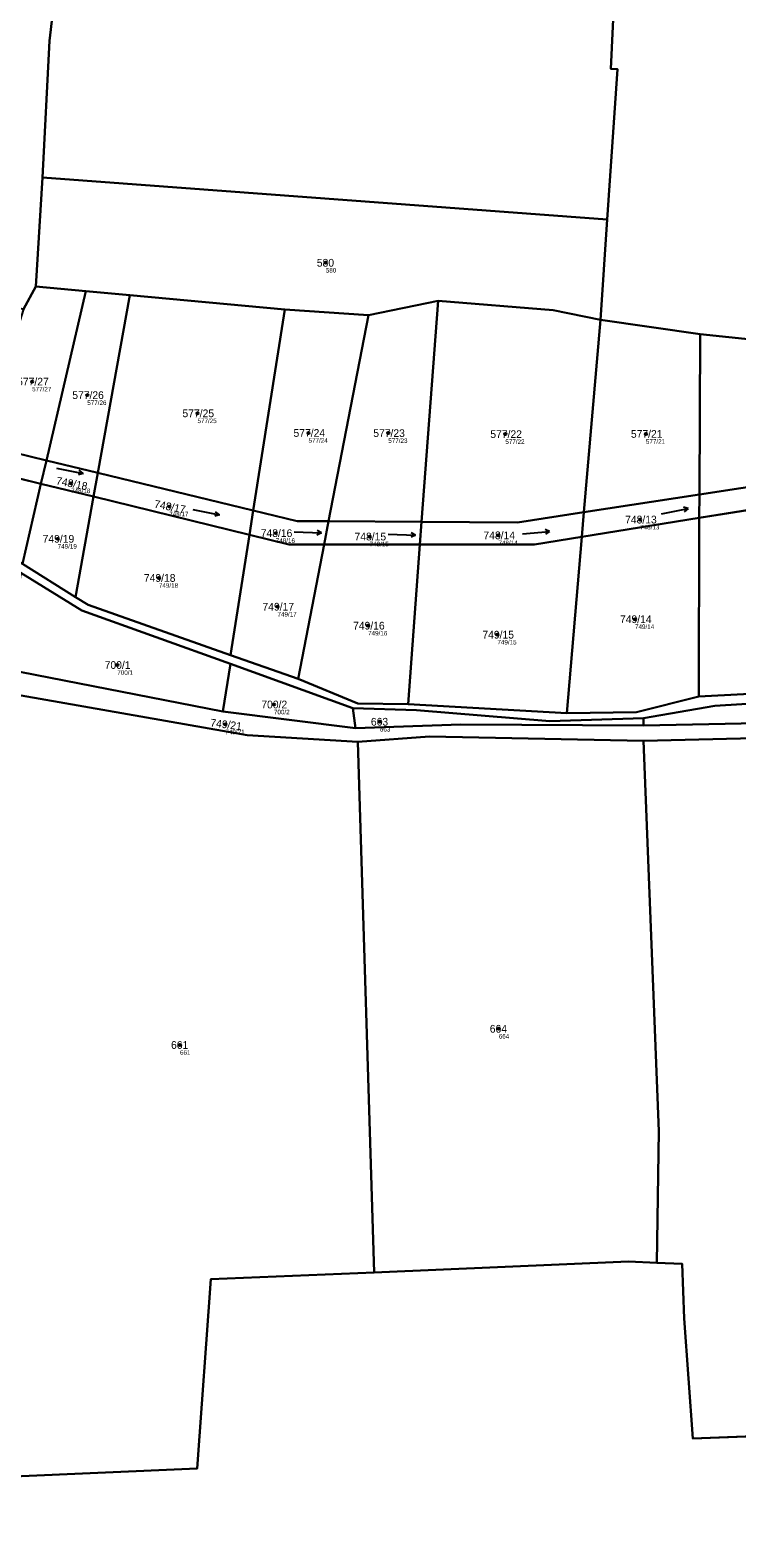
# Model space of a CAD drawing. Extents: x -767985 to -763816, y -1059600 to -1057360.
# Drawn here: x -764701.2 to -764545.8, y -1059400.7 to -1059068.8 of the extents above; entities that cross this region are included whole.
import ezdxf

# ---------------------------------------------------------------- set-up
doc = ezdxf.new("R2010")
doc.units = 0
for name, color, linetype in [('Definiční body', 7, 'Continuous'), ('Hranice parcel', 7, 'Continuous'), ('Parcelní čísla', 7, 'Continuous'), ('Polygon ku', 7, 'Continuous'), ('Polygon parcely', 7, 'Continuous'), ('Značky kultur', 7, 'Continuous')]:
    doc.layers.add(name, color=color, linetype=linetype)

msp = doc.modelspace()

# ---------------------------------------------------------------- linework, layer by layer
at = {"layer": 'Definiční body'}
for centre in [(-764636.2, -1059119.97994), (-764700.81, -1059146.14994), (-764688.68, -1059149.12994), (-764664.43, -1059153.12994), (-764640, -1059157.44994), (-764622.45, -1059157.48994), (-764596.69, -1059157.70994), (-764565.76, -1059157.65994), (-764692.24, -1059168.54994), (-764670.65, -1059173.64994), (-764567.03, -1059176.52994), (-764647.21, -1059179.50994), (-764626.57, -1059180.25994), (-764598.21, -1059179.99994), (-764695.2, -1059180.75994), (-764672.92, -1059189.37994), (-764646.83, -1059195.70994), (-764626.89, -1059199.87994), (-764568.16, -1059198.45994), (-764598.44, -1059201.86994), (-764682.08, -1059208.54994), (-764647.61, -1059217.23994), (-764658.3, -1059221.61994), (-764624.3, -1059221.03994), (-764598.14, -1059288.63994), (-764668.28, -1059292.20994)]:
    msp.add_circle(centre, 0.25, dxfattribs=at)
at = {"layer": 'Hranice parcel'}
for p, q in [((-764698.56, -1059101.24), (-764700.02, -1059125.18)), ((-764698.56, -1059101.24), (-764574.27, -1059110.44)), ((-764574.27, -1059110.44), (-764575.79, -1059132.56)), ((-764700.02, -1059125.18), (-764702.69, -1059130.2)), ((-764689.03, -1059126.2), (-764700.02, -1059125.18)), ((-764689.03, -1059126.2), (-764697.68, -1059163.49)), ((-764679.33, -1059127.1), (-764689.03, -1059126.2)), ((-764679.33, -1059127.1), (-764686.34, -1059166.24)), ((-764645.21, -1059130.25), (-764679.33, -1059127.1)), ((-764645.21, -1059130.25), (-764652.16, -1059174.51)), ((-764626.77, -1059131.54), (-764645.21, -1059130.25)), ((-764611.48, -1059128.39), (-764626.77, -1059131.54)), ((-764611.48, -1059128.39), (-764615.15, -1059177.01)), ((-764626.77, -1059131.54), (-764635.57, -1059176.88)), ((-764575.79, -1059132.56), (-764579.41, -1059174.89)), ((-764575.79, -1059132.56), (-764553.86, -1059135.67)), ((-764553.86, -1059135.67), (-764553.99, -1059170.98)), ((-764553.86, -1059135.67), (-764528.62, -1059138.32)), ((-764712.07, -1059160.01), (-764697.68, -1059163.49)), ((-764697.68, -1059163.49), (-764698.87, -1059168.63)), ((-764697.68, -1059163.49), (-764686.34, -1059166.24)), ((-764713.59, -1059165.02), (-764698.87, -1059168.63)), ((-764686.34, -1059166.24), (-764687.28, -1059171.47)), ((-764686.34, -1059166.24), (-764652.16, -1059174.51)), ((-764553.99, -1059170.98), (-764527.63, -1059166.93)), ((-764698.87, -1059168.63), (-764702.96, -1059186.26)), ((-764698.87, -1059168.63), (-764687.28, -1059171.47)), ((-764687.28, -1059171.47), (-764691.24, -1059193.61)), ((-764687.28, -1059171.47), (-764653, -1059179.87)), ((-764579.41, -1059174.89), (-764553.99, -1059170.98)), ((-764553.99, -1059170.98), (-764554.01, -1059176.16)), ((-764554.01, -1059176.16), (-764527.46, -1059171.89)), ((-764652.16, -1059174.51), (-764653, -1059179.87)), ((-764635.57, -1059176.88), (-764636.56, -1059181.99)), ((-764635.57, -1059176.88), (-764615.15, -1059177.01)), ((-764615.15, -1059177.01), (-764615.53, -1059181.99)), ((-764579.41, -1059174.89), (-764579.87, -1059180.32)), ((-764579.87, -1059180.32), (-764554.01, -1059176.16)), ((-764554.01, -1059176.16), (-764554.15, -1059215.5)), ((-764653, -1059179.87), (-764657.16, -1059206.4)), ((-764579.87, -1059180.32), (-764583.2, -1059219.14)), ((-764636.56, -1059181.99), (-764642.3, -1059211.57)), ((-764636.56, -1059181.99), (-764615.53, -1059181.99)), ((-764615.53, -1059181.99), (-764618.04, -1059217.14)), ((-764691.24, -1059193.61), (-764702.96, -1059186.26)), ((-764642.3, -1059211.57), (-764657.16, -1059206.4)), ((-764706.55, -1059209.46), (-764658.86, -1059218.75)), ((-764658.86, -1059218.75), (-764657.2, -1059208.32)), ((-764630.23, -1059218.04), (-764657.2, -1059208.32)), ((-764526.01, -1059214.01), (-764554.15, -1059215.5)), ((-764658.86, -1059218.75), (-764629.64, -1059222.47)), ((-764630.23, -1059218.04), (-764629.64, -1059222.47)), ((-764583.2, -1059219.14), (-764618.04, -1059217.14)), ((-764566.3, -1059221.83), (-764566.3, -1059220.23)), ((-764566.3, -1059221.83), (-764487.38, -1059220.24)), ((-764486.99, -1059223.34), (-764566.33, -1059225.21)), ((-764625.54, -1059342.27), (-764629.14, -1059225.48)), ((-764569.63, -1059339.9), (-764625.54, -1059342.27)), ((-764563.36, -1059340.15), (-764569.63, -1059339.9)), ((-764555.46, -1059378.83), (-764557.37, -1059352.47)), ((-764481.18, -1059376.08), (-764555.46, -1059378.83)), ((-764664.49, -1059385.45), (-764706.52, -1059387.29))]:
    msp.add_line(p, q, dxfattribs=at)
for points in [[(-764656.11, -1058892.9), (-764663.89, -1058913.48), (-764671.11, -1058955.98), (-764686.12, -1058988.7), (-764692.07, -1059028.92), (-764697.02, -1059071.13), (-764698.56, -1059101.24)], [(-764550.97, -1058937.86), (-764553.99, -1058960.4), (-764565.74, -1058995.14), (-764571.94, -1059044.52), (-764573.5, -1059077.29), (-764572, -1059077.35), (-764574.27, -1059110.44)], [(-764575.79, -1059132.56), (-764586.17, -1059130.4), (-764611.48, -1059128.39)], [(-764652.16, -1059174.51), (-764642.53, -1059176.84), (-764635.57, -1059176.88)], [(-764615.15, -1059177.01), (-764594, -1059177.14), (-764579.41, -1059174.89)], [(-764653, -1059179.87), (-764644.33, -1059181.99), (-764636.56, -1059181.99)], [(-764615.53, -1059181.99), (-764590.29, -1059181.99), (-764579.87, -1059180.32)], [(-764657.2, -1059208.32), (-764689.85, -1059196.56), (-764703.27, -1059188.28)], [(-764657.16, -1059206.4), (-764688.49, -1059195.33), (-764691.24, -1059193.61)], [(-764618.04, -1059217.14), (-764629.15, -1059217.04), (-764642.3, -1059211.57)], [(-764487.64, -1059213.64), (-764550.58, -1059217.53), (-764566.3, -1059220.23)], [(-764629.14, -1059225.48), (-764653.51, -1059223.97), (-764707.42, -1059214.53)], [(-764554.15, -1059215.5), (-764567.84, -1059218.95), (-764583.2, -1059219.14)], [(-764566.3, -1059220.23), (-764586.94, -1059220.92), (-764616.22, -1059218.5), (-764630.23, -1059218.04)], [(-764629.64, -1059222.47), (-764606.49, -1059221.61), (-764566.3, -1059221.83)], [(-764566.33, -1059225.21), (-764613.39, -1059224.32), (-764629.14, -1059225.48)], [(-764563.36, -1059340.15), (-764562.91, -1059311.18), (-764566.33, -1059225.21)], [(-764625.54, -1059342.27), (-764661.48, -1059343.79), (-764664.49, -1059385.45)], [(-764557.37, -1059352.47), (-764557.81, -1059340.38), (-764563.36, -1059340.15)]]:
    msp.add_lwpolyline(points, dxfattribs=at)
at = {"layer": 'Polygon ku'}
msp.add_lwpolyline([(-765043.67, -1059388.12), (-764964.54, -1059390.4), (-764964.68, -1059398.41), (-764961.64, -1059398.62), (-764931.25, -1059400.73), (-764893.65, -1059400.56), (-764857.18, -1059399.8), (-764821.02, -1059398.24), (-764822.93, -1059392.66), (-764790.27, -1059389.78), (-764787.27, -1059389.7), (-764746.26, -1059388.66), (-764725.57, -1059388.13), (-764706.52, -1059387.29), (-764664.49, -1059385.45), (-764661.48, -1059343.79), (-764625.54, -1059342.27), (-764569.63, -1059339.9), (-764563.36, -1059340.15), (-764557.81, -1059340.38), (-764557.37, -1059352.47), (-764555.46, -1059378.83), (-764481.18, -1059376.08)], dxfattribs=at)
at = {"layer": 'Polygon parcely'}
for points in [[(-764748.11, -1059013.19), (-764749.81, -1059022.37), (-764752.02, -1059034.29), (-764756.52, -1059058.65), (-764757.7, -1059074.31), (-764759.08, -1059120.3), (-764721.92, -1059124.44), (-764702.69, -1059130.2), (-764700.02, -1059125.18), (-764698.56, -1059101.24), (-764697.02, -1059071.13), (-764692.07, -1059028.92), (-764686.12, -1058988.7), (-764671.11, -1058955.98), (-764663.89, -1058913.48), (-764656.11, -1058892.9), (-764725.9, -1058866.15), (-764734.33, -1058914), (-764735.1, -1058926.49), (-764735.34, -1058930.33), (-764737.47, -1058965.18), (-764739.22, -1058976.45)], [(-764686.12, -1058988.7), (-764692.07, -1059028.92), (-764697.02, -1059071.13), (-764698.56, -1059101.24), (-764574.27, -1059110.44), (-764572, -1059077.35), (-764573.5, -1059077.29), (-764571.94, -1059044.52), (-764565.74, -1058995.14), (-764553.99, -1058960.4), (-764550.97, -1058937.86), (-764600.3, -1058914.3), (-764647.72, -1058896.12), (-764656.11, -1058892.9), (-764663.89, -1058913.48), (-764671.11, -1058955.98)], [(-764573.5, -1059077.29), (-764572, -1059077.35), (-764574.27, -1059110.44), (-764575.79, -1059132.56), (-764553.86, -1059135.67), (-764528.62, -1059138.32), (-764507.61, -1059139.04), (-764504.32, -1059119.13), (-764500.98, -1059107.77), (-764498.75, -1059094.63), (-764496.53, -1059064.78), (-764497.42, -1059020.24), (-764422.1, -1059006.07), (-764428.85, -1058998.23), (-764454.9, -1058979.8), (-764483.17, -1058963.28), (-764516.36, -1058954.39), (-764534.62, -1058947.71), (-764550.97, -1058937.86), (-764553.99, -1058960.4), (-764565.74, -1058995.14), (-764571.94, -1059044.52)], [(-764700.02, -1059125.18), (-764689.03, -1059126.2), (-764679.33, -1059127.1), (-764645.21, -1059130.25), (-764626.77, -1059131.54), (-764611.48, -1059128.39), (-764586.17, -1059130.4), (-764575.79, -1059132.56), (-764574.27, -1059110.44), (-764698.56, -1059101.24)], [(-764702.69, -1059130.2), (-764710.55, -1059154.97), (-764712.07, -1059160.01), (-764697.68, -1059163.49), (-764689.03, -1059126.2), (-764700.02, -1059125.18)], [(-764689.03, -1059126.2), (-764697.68, -1059163.49), (-764686.34, -1059166.24), (-764679.33, -1059127.1)], [(-764679.33, -1059127.1), (-764686.34, -1059166.24), (-764652.16, -1059174.51), (-764645.21, -1059130.25)], [(-764642.53, -1059176.84), (-764635.57, -1059176.88), (-764626.77, -1059131.54), (-764645.21, -1059130.25), (-764652.16, -1059174.51)], [(-764635.57, -1059176.88), (-764615.15, -1059177.01), (-764611.48, -1059128.39), (-764626.77, -1059131.54)], [(-764615.15, -1059177.01), (-764594, -1059177.14), (-764579.41, -1059174.89), (-764575.79, -1059132.56), (-764586.17, -1059130.4), (-764611.48, -1059128.39)], [(-764575.79, -1059132.56), (-764579.41, -1059174.89), (-764553.99, -1059170.98), (-764553.86, -1059135.67)], [(-764553.99, -1059170.98), (-764527.63, -1059166.93), (-764528.62, -1059138.32), (-764553.86, -1059135.67)], [(-764698.87, -1059168.63), (-764697.68, -1059163.49), (-764712.07, -1059160.01), (-764713.59, -1059165.02)], [(-764687.28, -1059171.47), (-764686.34, -1059166.24), (-764697.68, -1059163.49), (-764698.87, -1059168.63)], [(-764698.87, -1059168.63), (-764713.59, -1059165.02), (-764716.85, -1059175.82), (-764715.87, -1059177.87), (-764702.96, -1059186.26)], [(-764687.28, -1059171.47), (-764653, -1059179.87), (-764652.16, -1059174.51), (-764686.34, -1059166.24)], [(-764554.01, -1059176.16), (-764527.46, -1059171.89), (-764527.63, -1059166.93), (-764553.99, -1059170.98)], [(-764698.87, -1059168.63), (-764702.96, -1059186.26), (-764691.24, -1059193.61), (-764687.28, -1059171.47)], [(-764691.24, -1059193.61), (-764688.49, -1059195.33), (-764657.16, -1059206.4), (-764653, -1059179.87), (-764687.28, -1059171.47)], [(-764579.41, -1059174.89), (-764579.87, -1059180.32), (-764554.01, -1059176.16), (-764553.99, -1059170.98)], [(-764554.15, -1059215.5), (-764526.01, -1059214.01), (-764527.46, -1059171.89), (-764554.01, -1059176.16)], [(-764644.33, -1059181.99), (-764636.56, -1059181.99), (-764635.57, -1059176.88), (-764642.53, -1059176.84), (-764652.16, -1059174.51), (-764653, -1059179.87)], [(-764636.56, -1059181.99), (-764615.53, -1059181.99), (-764615.15, -1059177.01), (-764635.57, -1059176.88)], [(-764579.87, -1059180.32), (-764579.41, -1059174.89), (-764594, -1059177.14), (-764615.15, -1059177.01), (-764615.53, -1059181.99), (-764590.29, -1059181.99)], [(-764579.87, -1059180.32), (-764583.2, -1059219.14), (-764567.84, -1059218.95), (-764554.15, -1059215.5), (-764554.01, -1059176.16)], [(-764657.16, -1059206.4), (-764642.3, -1059211.57), (-764636.56, -1059181.99), (-764644.33, -1059181.99), (-764653, -1059179.87)], [(-764618.04, -1059217.14), (-764583.2, -1059219.14), (-764579.87, -1059180.32), (-764590.29, -1059181.99), (-764615.53, -1059181.99)], [(-764642.3, -1059211.57), (-764629.15, -1059217.04), (-764618.04, -1059217.14), (-764615.53, -1059181.99), (-764636.56, -1059181.99)], [(-764657.2, -1059208.32), (-764689.85, -1059196.56), (-764703.27, -1059188.28), (-764704.68, -1059197.37), (-764706.55, -1059209.46), (-764658.86, -1059218.75)], [(-764629.64, -1059222.47), (-764630.23, -1059218.04), (-764657.2, -1059208.32), (-764658.86, -1059218.75)], [(-764487.38, -1059220.24), (-764487.64, -1059213.64), (-764550.58, -1059217.53), (-764566.3, -1059220.23), (-764566.3, -1059221.83)], [(-764653.51, -1059223.97), (-764707.42, -1059214.53), (-764704.63, -1059349.3), (-764706.52, -1059387.29), (-764664.49, -1059385.45), (-764661.48, -1059343.79), (-764625.54, -1059342.27), (-764629.14, -1059225.48)], [(-764616.22, -1059218.5), (-764630.23, -1059218.04), (-764629.64, -1059222.47), (-764606.49, -1059221.61), (-764566.3, -1059221.83), (-764566.3, -1059220.23), (-764586.94, -1059220.92)], [(-764486.99, -1059223.34), (-764566.33, -1059225.21), (-764562.91, -1059311.18), (-764563.36, -1059340.15), (-764557.81, -1059340.38), (-764557.37, -1059352.47), (-764555.46, -1059378.83), (-764481.18, -1059376.08), (-764479.88, -1059331.75)], [(-764562.91, -1059311.18), (-764566.33, -1059225.21), (-764613.39, -1059224.32), (-764629.14, -1059225.48), (-764625.54, -1059342.27), (-764569.63, -1059339.9), (-764563.36, -1059340.15)]]:
    msp.add_lwpolyline(points, close=True, dxfattribs=at)
for points in [[(-764526.01, -1059214.01), (-764554.15, -1059215.5), (-764567.84, -1059218.95), (-764583.2, -1059219.14), (-764618.04, -1059217.14), (-764629.15, -1059217.04), (-764642.3, -1059211.57), (-764657.16, -1059206.4), (-764688.49, -1059195.33), (-764691.24, -1059193.61), (-764702.96, -1059186.26)], [(-764703.27, -1059188.28), (-764689.85, -1059196.56), (-764657.2, -1059208.32), (-764630.23, -1059218.04), (-764616.22, -1059218.5), (-764586.94, -1059220.92), (-764566.3, -1059220.23), (-764550.58, -1059217.53), (-764487.64, -1059213.64)], [(-764487.38, -1059220.24), (-764566.3, -1059221.83), (-764606.49, -1059221.61), (-764629.64, -1059222.47), (-764658.86, -1059218.75), (-764706.55, -1059209.46), (-764740.77, -1059204.21), (-764777.76, -1059201.7), (-764815.93, -1059196.03), (-764815.46, -1059201.74), (-764778.67, -1059205.63), (-764740.92, -1059208.29), (-764707.42, -1059214.53), (-764653.51, -1059223.97), (-764629.14, -1059225.48), (-764613.39, -1059224.32), (-764566.33, -1059225.21), (-764486.99, -1059223.34)]]:
    msp.add_lwpolyline(points, dxfattribs=at)
at = {"layer": 'Značky kultur'}
for p, q in [((-764695.47, -1059165.199), (-764689.58, -1059166.344)), ((-764689.58, -1059166.344), (-764690.635, -1059166.65)), ((-764689.58, -1059166.344), (-764690.443, -1059165.665)), ((-764556.457, -1059174.113), (-764557.512, -1059173.807)), ((-764665.46, -1059174.319), (-764659.57, -1059175.464)), ((-764659.57, -1059175.464), (-764660.625, -1059175.77)), ((-764659.57, -1059175.464), (-764660.433, -1059174.785)), ((-764562.346, -1059175.258), (-764556.457, -1059174.113)), ((-764556.457, -1059174.113), (-764557.32, -1059174.791)), ((-764643.141, -1059179.244), (-764637.145, -1059179.454)), ((-764637.145, -1059179.454), (-764638.139, -1059179.921)), ((-764637.145, -1059179.454), (-764638.104, -1059178.919)), ((-764622.451, -1059179.744), (-764616.455, -1059179.954)), ((-764616.455, -1059179.954), (-764617.449, -1059180.421)), ((-764616.455, -1059179.954), (-764617.414, -1059179.419)), ((-764592.921, -1059179.639), (-764586.944, -1059179.116)), ((-764586.944, -1059179.116), (-764587.961, -1059178.701)), ((-764586.944, -1059179.116), (-764587.873, -1059179.7))]:
    msp.add_line(p, q, dxfattribs=at)

# ---------------------------------------------------------------- texts
at = {"layer": 'Definiční body'}
for s, p in [('580', (-764636.2, -1059122.136)), ('577/27', (-764700.81, -1059148.306)), ('577/26', (-764688.68, -1059151.286)), ('577/25', (-764664.43, -1059155.286)), ('577/24', (-764640, -1059159.606)), ('577/23', (-764622.45, -1059159.646)), ('577/22', (-764596.69, -1059159.866)), ('577/21', (-764565.76, -1059159.816)), ('748/18', (-764692.24, -1059170.706)), ('748/17', (-764670.65, -1059175.806)), ('748/13', (-764567.03, -1059178.686)), ('749/19', (-764695.2, -1059182.916)), ('748/16', (-764647.21, -1059181.666)), ('748/15', (-764626.57, -1059182.416)), ('748/14', (-764598.21, -1059182.156)), ('749/18', (-764672.92, -1059191.536)), ('749/17', (-764646.83, -1059197.866)), ('749/14', (-764568.16, -1059200.616)), ('749/16', (-764626.89, -1059202.036)), ('749/15', (-764598.44, -1059204.026)), ('700/1', (-764682.08, -1059210.706)), ('700/2', (-764647.61, -1059219.396)), ('749/21', (-764658.3, -1059223.776)), ('663', (-764624.3, -1059223.196)), ('664', (-764598.14, -1059290.796)), ('661', (-764668.28, -1059294.366))]:
    msp.add_text(s, height=0.999996, dxfattribs=at).set_placement(p)
at = {"layer": 'Parcelní čísla'}
for s, p in [('580', (-764638.174, -1059120.83)), ('577/27', (-764704.115, -1059147)), ('577/26', (-764691.985, -1059149.98)), ('577/25', (-764667.735, -1059153.98)), ('577/24', (-764643.305, -1059158.3)), ('577/23', (-764625.755, -1059158.34)), ('577/22', (-764599.995, -1059158.56)), ('577/21', (-764569.065, -1059158.51)), ('748/13', (-764570.335, -1059177.38)), ('749/19', (-764698.505, -1059181.61)), ('748/16', (-764650.515, -1059180.36)), ('748/15', (-764629.875, -1059181.11)), ('748/14', (-764601.515, -1059180.85)), ('749/18', (-764676.225, -1059190.23)), ('749/17', (-764650.135, -1059196.56)), ('749/16', (-764630.195, -1059200.73)), ('749/14', (-764571.465, -1059199.31)), ('749/15', (-764601.745, -1059202.72)), ('700/1', (-764684.853, -1059209.4)), ('700/2', (-764650.383, -1059218.09)), ('663', (-764626.274, -1059221.89)), ('664', (-764600.114, -1059289.49)), ('661', (-764670.254, -1059293.06))]:
    msp.add_text(s, height=1.699998, dxfattribs=at).set_placement(p)
for s, rotation, p in [('748/18', 349, (-764695.647, -1059168.753)), ('748/17', 349, (-764674.057, -1059173.853)), ('749/21', 353, (-764661.684, -1059222.06))]:
    msp.add_text(s, height=1.699998, rotation=rotation, dxfattribs=at).set_placement(p)

doc.saveas('drawing.dxf')
